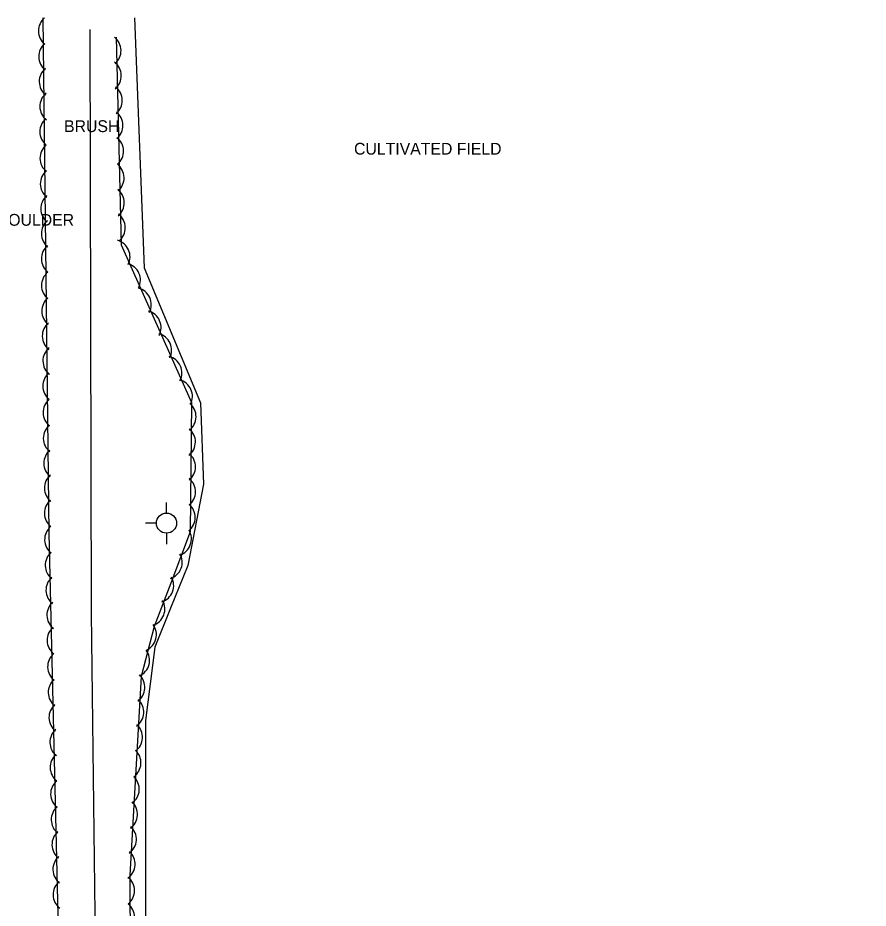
# Model space of a CAD drawing. Extents: x 1802180 to 1804859, y 572524 to 575172.
# Drawn here: x 1803529.6 to 1803709.6, y 574966.5 to 575155 of the extents above; entities that cross this region are included whole.
import ezdxf

# ---------------------------------------------------------------- set-up
doc = ezdxf.new("R2010")
doc.units = 0
for name, color, linetype in [('S_MISC_BOUNDARY', 7, 'Continuous'), ('S_MISC_BOUNDARY_ANNOT', 7, 'Continuous'), ('S_SHOULDER_ANNOT', 7, 'Continuous'), ('S_STREAM', 7, 'Continuous'), ('S_TREE', 7, 'Continuous'), ('S_TREE_ANNOT', 7, 'Continuous'), ('S_UTILITY_POLE', 7, 'Continuous')]:
    doc.layers.add(name, color=color, linetype=linetype)

msp = doc.modelspace()

# ---------------------------------------------------------------- linework, layer by layer
at = {"layer": 'S_MISC_BOUNDARY'}
msp.add_lwpolyline([(1803554.32, 575154.95), (1803556.36, 575102.06), (1803568.26, 575073.49), (1803568.9, 575056.23), (1803565.58, 575039.08), (1803561.89, 575030.01), (1803558.6, 575021.77), (1803556.64, 575006.26), (1803556.62, 574877.88), (1803709.56, 574875.46)], dxfattribs=at)
at = {"layer": 'S_STREAM'}
msp.add_lwpolyline([(1803544.83, 575152.51), (1803545.12, 575028.93), (1803546.27, 574936.37), (1803546.3, 574935.72)], dxfattribs=at)
at = {"layer": 'S_TREE'}
msp.add_lwpolyline([(1803550.41, 575150.9), (1803551.45, 575106.92), (1803566.38, 575073.55), (1803566.11, 575046.15), (1803562.02, 575035.31), (1803558.46, 575026.12), (1803555.73, 575015.57), (1803553.29, 574973.53), (1803553.62, 574909.08), (1803553.53, 574899.36), (1803550.98, 574893.84), (1803546.24, 574889.6), (1803542.7, 574890.19), (1803540.65, 574891.95), (1803539.41, 574895.75), (1803538.17, 574965.03), (1803536.26, 575045.86), (1803534.96, 575154.97)], dxfattribs=at)
for centre, start, end in [((1803537.61, 575152.19), 129.8864, 231.4833), ((1803537.67, 575146.76), 129.8864, 231.4833), ((1803547.83, 575148.02), 310.5563, 52.1532), ((1803537.77, 575141.48), 129.8864, 231.4833), ((1803547.88, 575142.71), 310.5563, 52.1532), ((1803548.08, 575137.44), 310.5563, 52.1532), ((1803537.91, 575136.21), 129.8864, 231.4833), ((1803548.24, 575132.16), 310.5563, 52.1532), ((1803537.9, 575130.89), 129.8864, 231.4833), ((1803548.36, 575126.73), 310.5563, 52.1532), ((1803537.93, 575125.26), 129.8864, 231.4833), ((1803548.47, 575121.1), 310.5563, 52.1532), ((1803538, 575119.84), 129.8864, 231.4833), ((1803548.52, 575115.79), 310.5563, 52.1532), ((1803538.1, 575114.55), 129.8864, 231.4833), ((1803538.23, 575109.28), 129.8864, 231.4833), ((1803548.72, 575110.52), 310.5563, 52.1532), ((1803538.22, 575103.96), 129.8864, 231.4833), ((1803549.73, 575104.37), 333.2939, 74.8908), ((1803551.94, 575099.42), 333.2939, 74.8908), ((1803538.26, 575098.33), 129.8864, 231.4833), ((1803554.21, 575094.26), 333.2939, 74.8908), ((1803538.32, 575092.91), 129.8864, 231.4833), ((1803556.31, 575089.38), 333.2939, 74.8908), ((1803538.42, 575087.62), 129.8864, 231.4833), ((1803558.53, 575084.6), 333.2939, 74.8908), ((1803538.55, 575082.36), 129.8864, 231.4833), ((1803560.72, 575079.79), 333.2939, 74.8908), ((1803538.54, 575077.04), 129.8864, 231.4833), ((1803562.93, 575074.83), 333.2939, 74.8908), ((1803538.58, 575071.41), 129.8864, 231.4833), ((1803563.7, 575070.53), 308.6407, 50.2376), ((1803538.64, 575065.98), 129.8864, 231.4833), ((1803563.57, 575065.21), 308.6407, 50.2376), ((1803538.74, 575060.7), 129.8864, 231.4833), ((1803563.59, 575059.94), 308.6407, 50.2376), ((1803538.87, 575055.43), 129.8864, 231.4833), ((1803563.58, 575054.65), 308.6407, 50.2376), ((1803538.87, 575050.11), 129.8864, 231.4833), ((1803563.52, 575049.23), 308.6407, 50.2376), ((1803538.92, 575044.51), 130.5537, 232.1506), ((1803562.72, 575044.68), 288.5045, 30.1014), ((1803539.04, 575039.09), 130.5537, 232.1506), ((1803560.77, 575039.73), 288.5045, 30.1014), ((1803539.2, 575033.8), 130.5537, 232.1506), ((1803558.97, 575034.8), 288.0591, 29.656), ((1803539.4, 575028.54), 130.5537, 232.1506), ((1803557.1, 575029.85), 288.0591, 29.656), ((1803539.45, 575023.22), 130.5537, 232.1506), ((1803555.31, 575024.42), 294.6774, 36.2743), ((1803539.55, 575017.59), 130.5537, 232.1506), ((1803553.87, 575018.98), 294.6774, 36.2743), ((1803552.86, 575013.25), 305.8827, 47.4797), ((1803539.68, 575012.17), 130.5537, 232.1506), ((1803552.63, 575007.99), 305.8827, 47.4797), ((1803539.84, 575006.88), 130.5537, 232.1506), ((1803540.03, 575001.62), 130.5537, 232.1506), ((1803552.36, 575002.7), 305.8827, 47.4797), ((1803540.09, 574996.3), 130.5537, 232.1506), ((1803552.04, 574997.29), 305.8827, 47.4797), ((1803540.19, 574990.67), 130.5537, 232.1506), ((1803551.68, 574991.67), 305.8827, 47.4797), ((1803540.31, 574985.25), 130.5537, 232.1506), ((1803551.3, 574986.36), 305.8827, 47.4797), ((1803551.07, 574981.1), 305.8827, 47.4797), ((1803540.47, 574979.96), 130.5537, 232.1506), ((1803550.8, 574975.82), 305.8827, 47.4797), ((1803540.67, 574974.7), 130.5537, 232.1506), ((1803550.69, 574970.23), 309.4937, 51.0906), ((1803540.72, 574969.38), 130.5537, 232.1506), ((1803550.68, 574964.6), 309.4937, 51.0906)]:
    msp.add_arc(centre, 3.63, start, end, dxfattribs=at)
at = {"layer": 'S_UTILITY_POLE'}
for p, q in [((1803561.08, 575050.13), (1803561.08, 575052.38)), ((1803558.99, 575048), (1803556.66, 575048)), ((1803561.16, 575043.58), (1803561.16, 575045.91))]:
    msp.add_line(p, q, dxfattribs=at)
msp.add_circle((1803561.08, 575048.02), 2.13, dxfattribs=at)

# ---------------------------------------------------------------- texts
at = {"layer": 'S_MISC_BOUNDARY_ANNOT'}
msp.add_text('CULTIVATED FIELD', height=2.5, dxfattribs=at).set_placement((1803600.76, 575126.01))
at = {"layer": 'S_SHOULDER_ANNOT'}
msp.add_text('PAVED SHOULDER', height=2.5, dxfattribs=at).set_placement((1803510.68, 575110.96))
at = {"layer": 'S_TREE_ANNOT'}
msp.add_text('BRUSH', height=2.5, dxfattribs=at).set_placement((1803539.4, 575130.79))

doc.saveas('drawing.dxf')
